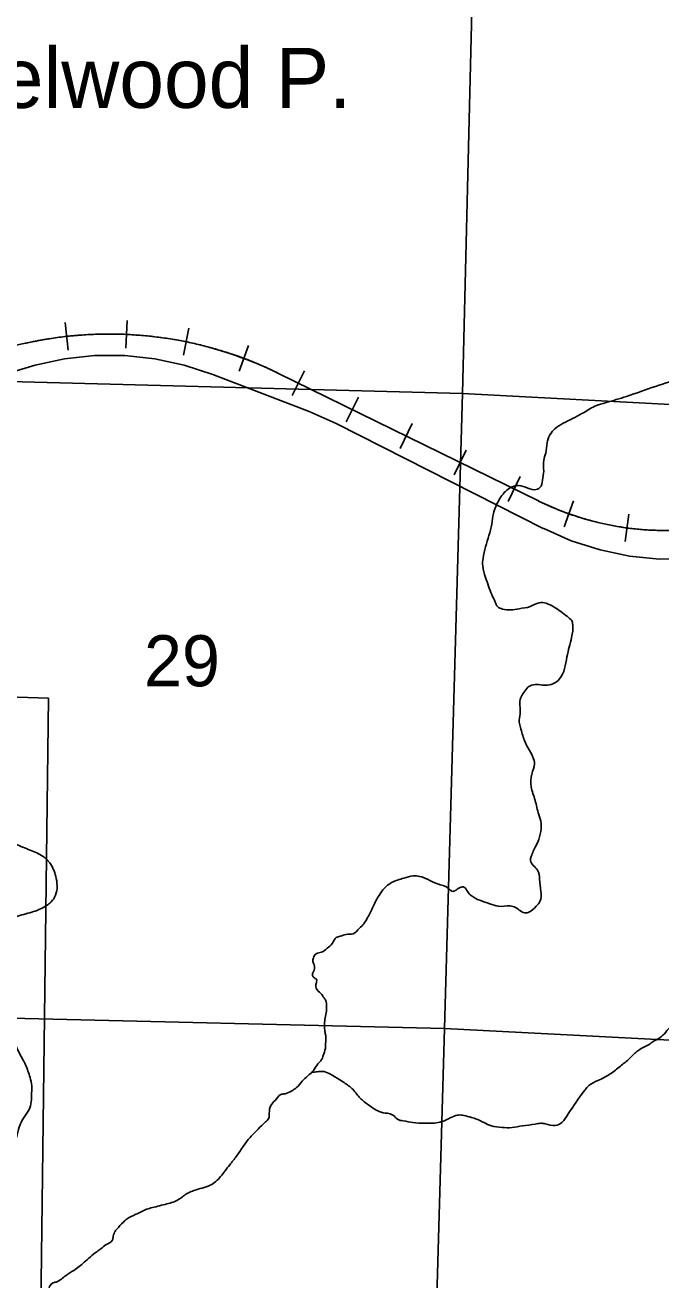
# Model space of a CAD drawing. Extents: x 1219626 to 1426462, y 456797 to 752399.
# Drawn here: x 1348140 to 1353434, y 566519 to 576968 of the extents above; entities that cross this region are included whole.
import ezdxf

# ---------------------------------------------------------------- set-up
doc = ezdxf.new("R2010")
doc.units = 0
for name, color, linetype in [('Cities Incorporated Area', 7, 'Continuous'), ('Narrow River Creek and Branch and Slough', 7, 'Continuous'), ('Narrow River Creek and Branch and Slough Text', 7, 'Continuous'), ('Railroads', 7, 'Continuous'), ('Section Lines', 7, 'Continuous'), ('Section Numbers', 7, 'Continuous')]:
    doc.layers.add(name, color=color, linetype=linetype)

msp = doc.modelspace()

# ---------------------------------------------------------------- linework, layer by layer
at = {"layer": 'Cities Incorporated Area'}
for p, q in [((1339773, 571677), (1348335, 571362)), ((1348335, 571362), (1348235, 563485))]:
    msp.add_line(p, q, dxfattribs=at)
at = {"layer": 'Narrow River Creek and Branch and Slough'}
for points in [[(1356527, 577057), (1356527, 576981), (1356558, 576891), (1356596, 576794), (1356621, 576728), (1356662, 576666), (1356659, 576583), (1356679, 576493), (1356711, 576437), (1356724, 576396), (1356704, 576347), (1356603, 576244), (1356462, 576102), (1356372, 576019), (1356285, 575908), (1356230, 575849), (1356060, 575721), (1355967, 575649), (1355936, 575617), (1355891, 575593), (1355870, 575524), (1355846, 575458), (1355756, 575379), (1355704, 575299), (1355659, 575192), (1355638, 575088), (1355611, 575046), (1355542, 575015), (1355467, 575008), (1355381, 574987), (1355274, 574956), (1355215, 574918), (1355163, 574838), (1355142, 574776), (1355101, 574686), (1355073, 574641), (1355021, 574596), (1354969, 574551), (1354910, 574513), (1354872, 574471), (1354814, 574444), (1354717, 574433), (1354668, 574433), (1354551, 574392), (1354437, 574347), (1354291, 574271), (1354170, 574184), (1354087, 574094), (1354046, 574042), (1354008, 573997), (1353973, 573994), (1353894, 574032), (1353797, 574046), (1353627, 574028), (1353389, 573959), (1353147, 573876), (1352977, 573824), (1352884, 573794), (1352776, 573732), (1352621, 573652), (1352552, 573607), (1352510, 573555), (1352486, 573490), (1352475, 573403), (1352458, 573344), (1352458, 573254), (1352448, 573178), (1352427, 573116), (1352382, 573099), (1352306, 573119), (1352230, 573133), (1352164, 573105), (1352085, 573012), (1352040, 572901), (1352026, 572811), (1352002, 572718), (1351953, 572527), (1351950, 572464), (1351974, 572368), (1352026, 572226), (1352054, 572163), (1352074, 572125), (1352116, 572105), (1352182, 572098), (1352254, 572108), (1352344, 572125), (1352420, 572157), (1352479, 572153), (1352545, 572122), (1352655, 572042), (1352693, 572011)], [(1352693, 572011), (1352700, 571973), (1352690, 571869), (1352652, 571707), (1352590, 571523), (1352534, 571482), (1352475, 571471), (1352358, 571471), (1352327, 571454), (1352292, 571409), (1352268, 571368), (1352261, 571233), (1352254, 571163), (1352265, 571118), (1352296, 571014), (1352327, 570952), (1352368, 570872), (1352382, 570817), (1352358, 570730), (1352354, 570626), (1352386, 570512), (1352417, 570395), (1352437, 570319), (1352437, 570274), (1352417, 570187), (1352392, 570132), (1352354, 570045), (1352348, 570011), (1352406, 569931), (1352424, 569855), (1352434, 569754), (1352427, 569671), (1352396, 569630), (1352334, 569581), (1352309, 569575), (1352223, 569620), (1352178, 569633), (1352081, 569630), (1352009, 569651), (1351853, 569720), (1351825, 569751), (1351794, 569789), (1351767, 569789), (1351728, 569765), (1351701, 569754), (1351666, 569779), (1351621, 569803), (1351573, 569817), (1351490, 569855), (1351424, 569879), (1351372, 569883), (1351293, 569865), (1351192, 569827), (1351147, 569796), (1351096, 569734), (1351061, 569675), (1351016, 569581), (1350992, 569536), (1350961, 569485), (1350923, 569447), (1350871, 569402), (1350812, 569395), (1350764, 569381), (1350730, 569370), (1350699, 569322), (1350654, 569280), (1350609, 569249), (1350564, 569235), (1350540, 569201), (1350536, 569169), (1350546, 569142), (1350550, 569121), (1350546, 569097), (1350536, 569076), (1350533, 569059), (1350543, 569038), (1350567, 569021), (1350567, 569000), (1350560, 568972), (1350564, 568948), (1350602, 568903), (1350629, 568868), (1350643, 568844), (1350650, 568799), (1350647, 568744), (1350636, 568688), (1350633, 568637), (1350636, 568588), (1350643, 568553), (1350643, 568502), (1350640, 568446)], [(1346514, 571407), (1346673, 571385), (1346877, 571340), (1347043, 571291), (1347195, 571226), (1347309, 571163), (1347399, 571098), (1347468, 570980), (1347486, 570831), (1347482, 570693), (1347461, 570464), (1347468, 570402), (1347531, 570354), (1347724, 570305), (1347935, 570215), (1348060, 570149), (1348181, 570098), (1348289, 570045), (1348351, 569983), (1348399, 569862), (1348406, 569779), (1348386, 569706), (1348347, 569657), (1348309, 569630), (1348254, 569602), (1348195, 569581), (1348064, 569543), (1348012, 569519), (1347967, 569471), (1347943, 569422), (1347946, 569280), (1347946, 569208), (1347939, 569163), (1347922, 569055), (1347894, 568882), (1347877, 568785), (1347894, 568730), (1347960, 568654), (1348085, 568422), (1348143, 568311), (1348181, 568204), (1348195, 568135), (1348195, 568093), (1348178, 567951), (1348098, 567813), (1348074, 567726), (1348047, 567650), (1347984, 567480), (1347898, 567294), (1347846, 567155), (1347818, 567024), (1347836, 566937), (1347856, 566809), (1347908, 566667), (1347964, 566557), (1348002, 566508), (1348040, 566463), (1348060, 566380), (1348077, 566347)], [(1354014, 568840), (1353948, 568847), (1353882, 568830), (1353823, 568798), (1353716, 568722), (1353668, 568691), (1353561, 568660), (1353519, 568632), (1353426, 568535), (1353370, 568504), (1353336, 568480), (1353249, 568432), (1353218, 568407), (1353173, 568362), (1353097, 568300), (1353011, 568234), (1352910, 568179), (1352834, 568137), (1352803, 568103), (1352686, 567937), (1352637, 567864), (1352610, 567830), (1352554, 567805), (1352471, 567819), (1352433, 567823), (1352388, 567816), (1352281, 567802), (1352195, 567788), (1352112, 567788), (1352022, 567802), (1351901, 567857), (1351856, 567871), (1351793, 567888), (1351748, 567892), (1351707, 567881), (1351652, 567854), (1351593, 567833), (1351472, 567823), (1351368, 567830), (1351289, 567843), (1351240, 567857), (1351202, 567892), (1351157, 567906), (1351088, 567920), (1351040, 567947), (1350963, 568003), (1350901, 568065), (1350868, 568106), (1350796, 568162), (1350713, 568214), (1350671, 568238), (1350616, 568255), (1350571, 568252), (1350526, 568248)], [(1350640, 568446), (1350623, 568387), (1350609, 568353), (1350578, 568318), (1350540, 568263), (1350446, 568173), (1350401, 568121), (1350360, 568093), (1350304, 568069), (1350270, 568062), (1350221, 568014), (1350187, 567972), (1350173, 567906), (1350169, 567865), (1350142, 567834), (1350080, 567775), (1350014, 567706), (1349900, 567550), (1349844, 567477), (1349803, 567425), (1349729, 567339), (1349681, 567308), (1349546, 567263), (1349459, 567218), (1349421, 567190), (1349321, 567152), (1349200, 567121), (1349152, 567107), (1349062, 567065), (1348989, 567027), (1348958, 567000), (1348903, 566941), (1348885, 566917), (1348872, 566872), (1348865, 566847), (1348816, 566813), (1348771, 566778), (1348737, 566754), (1348633, 566667), (1348546, 566598), (1348481, 566557), (1348443, 566526), (1348398, 566501), (1348367, 566491), (1348339, 566453), (1348318, 566377), (1348303, 566344)]]:
    msp.add_spline(points, degree=3, dxfattribs=at)
at = {"layer": 'Railroads'}
for p, q in [((1348473, 574490), (1348499, 574261)), ((1348991, 574507), (1348980, 574277)), ((1349504, 574443), (1349458, 574218)), ((1350001, 574300), (1349921, 574085)), ((1350505, 573751), (1349704, 574058)), ((1350251, 574067), (1352414, 573005)), ((1350467, 574089), (1350365, 573883)), ((1350916, 573869), (1350814, 573663)), ((1352453, 572777), (1350731, 573651)), ((1351364, 573649), (1351263, 573442)), ((1351813, 573428), (1351712, 573222)), ((1352262, 573208), (1352161, 573001)), ((1352705, 573007), (1352628, 572790)), ((1353167, 572895), (1353136, 572667))]:
    msp.add_line(p, q, dxfattribs=at)
for points in [[(1347420, 574156), (1348140, 574318), (1348156, 574321), (1348171, 574324), (1348187, 574328), (1348202, 574331), (1348218, 574334), (1348234, 574337), (1348250, 574340), (1348265, 574343), (1348281, 574346), (1348297, 574349), (1348313, 574351), (1348328, 574354), (1348344, 574356), (1348360, 574359), (1348376, 574361), (1348392, 574364), (1348408, 574366), (1348423, 574368), (1348439, 574370), (1348455, 574372), (1348471, 574374), (1348487, 574376), (1348503, 574377), (1348519, 574379), (1348535, 574381), (1348551, 574382), (1348567, 574383), (1348582, 574385), (1348598, 574386), (1348614, 574387), (1348630, 574388), (1348646, 574389), (1348662, 574390), (1348678, 574391), (1348694, 574392), (1348710, 574392), (1348726, 574393), (1348742, 574394), (1348758, 574394), (1348774, 574394), (1348790, 574395), (1348806, 574395), (1348822, 574395), (1348838, 574395), (1348854, 574395), (1348870, 574395), (1348886, 574395), (1348902, 574395), (1348918, 574394), (1348934, 574394), (1348950, 574393), (1348966, 574393), (1348982, 574392), (1348998, 574391), (1349014, 574390), (1349030, 574389), (1349046, 574389), (1349062, 574387), (1349078, 574386), (1349094, 574385)], [(1349094, 574385), (1349110, 574384), (1349126, 574382), (1349142, 574381), (1349158, 574379), (1349174, 574378), (1349189, 574376), (1349205, 574374), (1349221, 574372), (1349237, 574370), (1349253, 574368), (1349269, 574366), (1349285, 574364), (1349301, 574362), (1349316, 574360), (1349332, 574357), (1349348, 574355), (1349364, 574352), (1349380, 574349), (1349395, 574347), (1349411, 574344), (1349427, 574341), (1349443, 574338), (1349458, 574335), (1349474, 574332), (1349490, 574329), (1349505, 574325), (1349521, 574322), (1349537, 574318), (1349552, 574315), (1349568, 574311), (1349583, 574308), (1349599, 574304), (1349614, 574300), (1349630, 574296), (1349645, 574292), (1349661, 574288), (1349676, 574284), (1349692, 574280), (1349707, 574275), (1349723, 574271), (1349738, 574267), (1349753, 574262), (1349769, 574257), (1349784, 574253), (1349799, 574248), (1349814, 574243), (1349830, 574238), (1349845, 574233), (1349860, 574228), (1349875, 574223), (1349890, 574218), (1349905, 574213), (1349921, 574207), (1349936, 574202), (1349951, 574196), (1349966, 574191), (1349981, 574185), (1349996, 574179), (1350010, 574173), (1350025, 574168), (1350040, 574162), (1350055, 574156), (1350070, 574150), (1350084, 574143), (1350099, 574137), (1350114, 574131), (1350129, 574124), (1350143, 574118), (1350158, 574111), (1350172, 574105), (1350187, 574098), (1350201, 574091), (1350216, 574084), (1350230, 574077), (1350245, 574070), (1350251, 574067), (1352414, 573005), (1352427, 572999), (1352439, 572993), (1352452, 572987), (1352464, 572981), (1352477, 572975), (1352489, 572970), (1352502, 572964), (1352515, 572959), (1352527, 572953), (1352540, 572948), (1352553, 572942), (1352566, 572937), (1352579, 572932), (1352592, 572927), (1352604, 572922), (1352617, 572917), (1352630, 572912), (1352643, 572907), (1352656, 572902), (1352669, 572898), (1352682, 572893), (1352696, 572888), (1352709, 572884)], [(1349704, 574058), (1349465, 574136), (1349219, 574188), (1348969, 574215), (1348718, 574215), (1348468, 574188), (1348223, 574136), (1348057, 574085)], [(1350731, 573651), (1350505, 573751)], [(1352709, 572884), (1352722, 572880), (1352735, 572875), (1352748, 572871), (1352761, 572867), (1352775, 572863), (1352788, 572859), (1352801, 572855), (1352815, 572851), (1352828, 572847), (1352841, 572844), (1352855, 572840), (1352868, 572837), (1352881, 572833), (1352895, 572830), (1352908, 572826), (1352922, 572823), (1352935, 572820), (1352949, 572817), (1352962, 572814), (1352976, 572811), (1352989, 572808), (1353003, 572806), (1353017, 572803), (1353030, 572800), (1353044, 572798), (1353058, 572795), (1353071, 572793), (1353085, 572791), (1353099, 572789), (1353112, 572786), (1353126, 572784), (1353140, 572782), (1353153, 572781), (1353167, 572779), (1353181, 572777), (1353195, 572775), (1353208, 572774), (1353222, 572772), (1353236, 572771), (1353250, 572770), (1353264, 572768), (1353277, 572767), (1353291, 572766), (1353305, 572765), (1353319, 572764), (1353333, 572763), (1353346, 572763), (1353360, 572762), (1353374, 572761), (1353388, 572761), (1353402, 572760), (1353416, 572760), (1353430, 572760), (1353443, 572760)], [(1354408, 572681), (1354169, 572602), (1353924, 572549), (1353674, 572522), (1353423, 572521), (1353173, 572546), (1352927, 572597), (1352688, 572674), (1352458, 572775), (1352453, 572777)]]:
    msp.add_lwpolyline(points, dxfattribs=at)
for centre, radius, start, end in [((1348840, 571195), 3200, 63.8455, 102.6415), ((1353472, 575159), 2400, 243.8455, 296.4187)]:
    msp.add_arc(centre, radius, start, end, dxfattribs=at)
at = {"layer": 'Section Lines'}
for p, q in [((1351782, 573901), (1351911, 579166)), ((1351782, 573901), (1346486, 574039)), ((1351631, 568611), (1351782, 573901)), ((1357114, 573616), (1351782, 573901)), ((1346368, 568739), (1351631, 568611)), ((1351486, 563371), (1351631, 568611)), ((1351631, 568611), (1356964, 568339))]:
    msp.add_line(p, q, dxfattribs=at)

# ---------------------------------------------------------------- texts
at = {"layer": 'Narrow River Creek and Branch and Slough Text'}
msp.add_text('Hazelwood P.', height=500, rotation=359.9998, dxfattribs=at).set_placement((1346732, 576278))
at = {"layer": 'Section Numbers'}
msp.add_text('29', height=425, rotation=359.9998, dxfattribs=at).set_placement((1349130, 571462))

doc.saveas('drawing.dxf')
